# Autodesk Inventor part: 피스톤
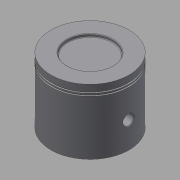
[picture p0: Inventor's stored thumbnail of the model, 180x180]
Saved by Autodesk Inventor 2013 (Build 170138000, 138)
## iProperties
Created: 2016-11
Part Number: 피스톤
Material: 강철, 탄소
Document SubType Name: Modeling
Designer: mduedu
Density: 7.87 g/cm^3
Mass: 410.138 g
Surface Area: 237.506 cm^2
Volume: 52.1141 cm^3
Author: mduedu
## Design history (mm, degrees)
sketch "스케치1"
  geometry: C1 r 30 at (0, 0); 1 further point
  constraints: 1 centre point, 1 coincident
  dimensions: "d0" = 60 diameter of C1
extrude "돌출1" new body sketch "스케치1" distance "d1" = 50; taper "d2" = 0 deg
sketch "스케치2"
  geometry: C1 r 28 at (0, 0); 1 further point
  constraints: 1 centre point, 1 coincident
  dimensions: "d3" = 56 diameter of C1
extrude "돌출2" cut sketch "스케치2" distance "d4" = 45; taper "d5" = 0 deg
sketch "스케치3"
  geometry: L1 (30, 0)-(30, 50) reference; L2 (30, 45)-(29, 45); L3 (29, 45)-(29, 44); L4 (29, 44)-(30, 44); L5 (30, 44)-(30, 45); L6 (30, 43)-(29, 43); L7 (29, 43)-(29, 42); L8 (29, 42)-(30, 42); L9 (30, 42)-(30, 43); L10 (30, 50)-(-30, 50) reference; L11 (0, 50)-(0, 0)
  constraints: 18 end point, 4 parallel, 3 equal length, 3 perpendicular, 2 horizontal, 2 point on line, 1 midpoint
  dimensions: "d6" = 1 distance of L2.start L2.end; "d8" = 5 distance between parallel lines of L10 L2; "d9" = 1 distance between parallel lines of L6 L4
revolve "회전1" sketch "스케치3" stored, may be unused: angle "d10" = 90 deg
node "작업 평면1"
sketch "스케치4"
  geometry: L1 (0, -22.978)-(45, -22.978) reference; L2 (45, -22.978)-(45, 22.978) reference; L3 (45, 22.978)-(0, 22.978) reference; L4 (0, 22.978)-(0, 25.377) reference; L5 (0, 25.377)-(42, 25.377) reference; L6 (42, 25.377)-(42, 24.187) reference; L7 (42, 24.187)-(43, 24.187) reference; L8 (43, 24.187)-(43, 25.377) reference; L9 (43, 25.377)-(44, 25.377) reference; L10 (44, 25.377)-(44, 24.187) reference; L11 (44, 24.187)-(45, 24.187) reference; L12 (45, 24.187)-(45, 25.377) reference; L13 (45, 25.377)-(50, 25.377) reference; L14 (50, 25.377)-(50, -25.377) reference; L15 (50, -25.377)-(45, -25.377) reference; L16 (45, -25.377)-(45, -24.187) reference; L17 (45, -24.187)-(44, -24.187) reference; L18 (44, -24.187)-(44, -25.377) reference; L19 (44, -25.377)-(43, -25.377) reference; L20 (43, -25.377)-(43, -24.187) reference; L21 (43, -24.187)-(42, -24.187) reference; L22 (42, -24.187)-(42, -25.377) reference; L23 (42, -25.377)-(0, -25.377) reference; L24 (0, -25.377)-(0, -22.978) reference; L25 (12.5, 22.978)-(45, 22.978); L26 (45, 22.978)-(45, -22.978); L27 (45, -22.978)-(12.5, -22.978); L28 (12.5, -22.978)-(12.5, 22.978); C1 r 7.5 at (20, 0); C2 r 4 at (20, 0); 1 further point
  constraints: 8 end point, 2 centre point, 2 parallel, 1 coincident, 1 horizontal, 1 horizontal alignment, 1 perpendicular, 1 point on line, 1 tangent
  dimensions: "d12" = 15 diameter of C1; "d13" = 8 diameter of C2; "d14" = 20 distance of point (0, 0) C1.centre
  node "절단 모서리 투영1"
extrude "돌출3" join sketch "스케치4" stored distance "d15" = 11.75; taper "d16" = 0 deg
extrude "돌출4" cut sketch "스케치4" stored distance "d17" = 72; taper "d18" = 0 deg
fillet "모깎기2" dims "d20" = 3
chamfer "모따기1" distance "d21" = 0.5; stored, may be unused: second distance "d22" = 2, angle "d23" = 45 deg
chamfer "모따기2" distance "d24" = 0.5; stored, may be unused: second distance "d25" = 2, angle "d26" = 45 deg
sketch "스케치5"
  geometry: C1 r 17.5 at (0, 0); 1 further point
  constraints: 1 centre point, 1 coincident
  dimensions: "d27" = 35 diameter of C1
extrude "돌출5" cut sketch "스케치5" distance "d28" = 2; taper "d29" = 0 deg
fillet "모깎기3" dims "d30" = 0.5
node "솔리드1"
mirror "대칭1"
other parameters: "d11" = -16
